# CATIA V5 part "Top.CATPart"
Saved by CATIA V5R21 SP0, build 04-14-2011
Part number: Part1.1
Bounding box of the stored display mesh (mm): x -50 to 50, y -25 to 25, z -20 to 10
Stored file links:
  D:\CATIA V5R21 E-RESOURCES\CATIA-V5R21\catia-v5r21-prt\c12-catia-v5r20-prt\c12-catia-v5-r20-figr-12-8\cat_v5r21_Top.CATPart
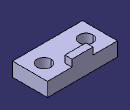
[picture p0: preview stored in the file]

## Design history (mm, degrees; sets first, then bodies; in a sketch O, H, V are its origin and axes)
Body1 (main body)
  Sketch1 on xy-plane, origin (0, 0, 0), H (1, 0, 0), V (0, 1, 0)
    line L1 (50, 25) -> (50, -25)
    line L2 (50, -25) -> (-50, -25)
    line L3 (-50, -25) -> (-50, 25)
    line L4 (-50, 25) -> (50, 25)
    circle A1 centre (-30, 0) radius 10
    point P5 (-30, 0)
    circle A2 centre (30, 0) radius 10
    length L2 = 100
    length L1 = 50
    radius A1 = 10
    distance P5 V = 30
    vertical: L1 V, L3 V
    horizontal: L2 H, L4 H
    equidistance: L1 L3 O, L2 L4 O
    coincidence: P5 H
    symmetry: A1 A2 V
  Pad1: profile Sketch1, direction (0, 0, -1), length 20
  Sketch2 on face of Pad1, origin (0, 0, 0), H (1, 0, 0), V (0, 1, 0)
    line L1 (-15, 25) -> (15, 25)
    line L2 (15, 25) -> (15, 15)
    line L3 (15, 15) -> (-15, 15)
    line L4 (-15, 15) -> (-15, 25)
    reference projected line E1 (50, 25) -> (-50, 25) from edge [face of Pad1 | face of Pad1]
    length L1 = 30
    distance L4 V = 15
    length L2 = 10
    horizontal: L1 H, L3 H
    vertical: L2 V, L4 V
    coincidence: L1 E1
  Pad2: profile Sketch2, direction (0, 0, 1), length 10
